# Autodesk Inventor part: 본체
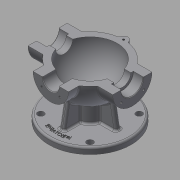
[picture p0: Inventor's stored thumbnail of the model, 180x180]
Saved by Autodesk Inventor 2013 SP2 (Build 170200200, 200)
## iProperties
Created: 2015-12
Part Number: 본체
Material: 일반
Document SubType Name: Modeling
Designer: mduedu
Density: 1 g/cm^3
Author: mduedu
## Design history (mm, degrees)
sketch "스케치1"
  geometry: L1 (-53, 0)-(53, 0); A1 r 53 centre (0, 0) between (53, 0) and (-53, 0); 2 further points
  constraints: 2 coincident, 2 end point, 2 point on circle, 1 centre point, 1 horizontal, 1 midpoint
  dimensions: "d0" = 53 radius of A1
revolve "회전1" sketch "스케치1" stored, may be unused: angle "d2" = 90 deg
feature "쉘1" dims "d11" = 10
node "작업 평면1"
sketch "스케치2"
  geometry: C1 r 31 at (0, 0); 1 further point
  constraints: 1 centre point, 1 coincident
  dimensions: "d4" = 62 diameter of C1
extrude "돌출1" join sketch "스케치2" stored distance "d5" = 10; taper "d6" = 0 deg
node "작업 평면2"
sketch "스케치3"
  geometry: C1 r 28 at (0, 0); 1 further point
  constraints: 1 centre point, 1 coincident
  dimensions: "d8" = 56 diameter of C1
extrude "돌출2" join sketch "스케치3" stored distance "d9" = 10; taper "d10" = 0 deg
hole "구멍1" diameter "d14" = 35; stored, may be unused: countersink angle "d18" = 90 deg, drill point angle "d20" = 0 deg; dims "d12" = 10, "d13" = 10, "d15" = 6, "d16" = 4, "d17" = 2, "d19" = 16
hole "구멍2" diameter "d23" = 27; stored, may be unused: countersink angle "d27" = 90 deg, drill point angle "d29" = 0 deg; dims "d21" = 10, "d22" = 10, "d24" = 6, "d25" = 4, "d26" = 2, "d28" = 16
fillet "모깎기1" dims "d30" = 0.3
hole "구멍3" diameter "d33" = 26; stored, may be unused: countersink angle "d37" = 90 deg, drill point angle "d39" = 0 deg; dims "d31" = 10, "d32" = 10, "d34" = 6, "d35" = 4, "d36" = 2, "d38" = 16
chamfer "모따기1" distance "d40" = 1; stored, may be unused: second distance "d41" = 2, angle "d42" = 45 deg
sketch "스케치4"
  geometry: L1 (0, 0)-(0, -25); L2 (0, 0)-(-17.678, -17.678); A1 r 25 centre (0, 0) between (-17.678, -17.678) and (0, -25); 1 further point
  constraints: 4 end point, 2 point on circle, 1 centre point, 1 coincident, 1 vertical
  dimensions: "d43" = 50 diameter of A1; "d47" = 45 deg angle of L1 L2
hole "구멍4" sketch "스케치4" at (-17.678, -17.678) diameter "d49" = 3.242; stored, may be unused: countersink angle "d53" = 90 deg, drill point angle "d55" = 118 deg; dims "d50" = 11, "d51" = 4, "d52" = 2, "d54" = 13
sketch "스케치5"
  geometry: L1 (0, 0)-(0, -20); L2 (0, 0)-(-14.142, -14.142); A1 r 20 centre (0, 0) between (0, -20) and (-14.142, -14.142); 2 further points
  constraints: 4 end point, 2 coincident, 2 point on circle, 1 centre point, 1 vertical
  dimensions: "d59" = 40 diameter of A1; "d65" = 45 deg angle of L1 L2
hole "구멍5" sketch "스케치5" at (-14.142, -14.142) diameter "d67" = 3.242; stored, may be unused: countersink angle "d71" = 90 deg, drill point angle "d73" = 118 deg; dims "d68" = 8, "d69" = 4, "d70" = 2, "d72" = 10
node "작업 평면3"
sketch "스케치6"
  geometry: C1 r 65 at (0, 0); 1 further point
  constraints: 1 centre point, 1 coincident
  dimensions: "d78" = 130 diameter of C1
extrude "돌출3" join sketch "스케치6" distance "d80" = 10; taper "d81" = 0 deg
sketch "스케치7"
  geometry: C1 r 20 at (0, 0); 1 further point
  constraints: 1 centre point, 1 coincident
  dimensions: "d82" = 40 diameter of C1
extrude "돌출4" join sketch "스케치7" stored distance "d84" = 10; taper "d85" = 0 deg
sketch "스케치8"
  geometry: 2 further points
  constraints: 1 coincident
hole "구멍6" sketch "스케치8" at (0, 0) diameter "d86" = 20; stored, may be unused: countersink angle "d90" = 90 deg, drill point angle "d92" = 118 deg; dims "d87" = 7, "d88" = 40, "d89" = 5, "d91" = 10
fillet "모깎기2" dims "d93" = 0.3
sketch "스케치9"
  geometry: L1 (65, -75)-(-65, -75) reference; L2 (-45, -75)-(-38.245, -36.692); A1 r 53 centre (0, 0) between (42.988, 31) and (42.988, -31) reference; 1 further point
  constraints: 2 end point, 1 point on circle, 1 point on line
  dimensions: "d94" = 45 horizontal distance of L2.start point (0, 0); "d95" = 80 deg angle of L2 L1
feature "리브1" sketch "스케치9" dims "d96" = 1, "d97" = 8, "d98" = 0, "d99" = 0, "d100" = 1, "d101" = 1
sketch "스케치10"
  geometry: L1 (0, 0)-(0, -55); L2 (0, 0)-(-38.891, -38.891); A1 r 55 centre (0, 0) between (0, -55) and (-38.891, -38.891); 2 further points
  constraints: 4 end point, 2 coincident, 2 point on circle, 1 centre point, 1 vertical
  dimensions: "d105" = 110 diameter of A1; "d107" = 45 deg angle of L1 L2
hole "구멍7" sketch "스케치10" at (-38.891, -38.891) diameter "d109" = 10; stored, may be unused: countersink angle "d113" = 90 deg, drill point angle "d115" = 118 deg; dims "d110" = 7, "d111" = 40, "d112" = 5, "d114" = 10
fillet "모깎기3" dims "d120" = 3
fillet "모깎기4" dims "d121" = 3, "d122" = 3
fillet "모깎기5" dims "d123" = 3
fillet "모깎기6" dims "d124" = 3
sketch "스케치11"
  geometry: C1 r 5 at (-38.891, 38.891) reference; C2 r 5 at (38.891, 38.891) reference; C3 r 5 at (38.891, -38.891) reference; C4 r 5 at (-38.891, -38.891) reference; C5 r 20 at (0, 0) reference; C6 r 65 at (0, 0) reference; 1 further point
  constraints: 3 other
feature "엠보싱1" sketch "스케치11" dims "d125" = 0.5, "d126" = 0
sketch "스케치12"
  geometry: L1 (0, 100)-(0, -100); L2 (0, 100)-(100, 100); L3 (100, 100)-(100, -100); L4 (100, -100)-(0, -100); 2 further points
  constraints: 8 end point, 3 perpendicular, 1 coincident, 1 midpoint, 1 vertical
  dimensions: "d127" = 200 distance of L2.end L3.end; "d129" = 100 distance between parallel lines of L1 L3
extrude "돌출5" cut sketch "스케치12" stored distance "d130" = 10; taper "d131" = 0 deg
sketch "스케치13"
  geometry: C1 r 7 at (0, 53); A1 r 53 centre (0, 0) between (42.113, 32.179) and (-42.113, 32.179) reference; 1 further point
  constraints: 1 centre point, 1 point on circle
  dimensions: "d132" = 14 diameter of C1
extrude "돌출6" join sketch "스케치13" distance "d134" = 15; taper "d135" = 0 deg
hole "구멍8" diameter "d139" = 3.242; stored, may be unused: countersink angle "d143" = 90 deg, drill point angle "d145" = 118 deg; dims "d140" = 8, "d141" = 4, "d142" = 2, "d144" = 10, "d148" = 10, "d149" = 10
fillet "모깎기7" dims "d146" = 3
fillet "모깎기8" dims "d147" = 3
node "솔리드1"
mirror "대칭1"
mirror "대칭2"
pattern_circular "원형 패턴1" dims angle "d57" = 360 deg
mirror "대칭3"
pattern_circular "원형 패턴2" dims angle "d75" = 360 deg
pattern_circular "원형 패턴3" dims angle "d103" = 360 deg
pattern_circular "원형 패턴4" dims angle "d118" = 360 deg
node "투영된 루프1"
other parameters: "d3" = 67, "d7" = 62, "d77" = -85
